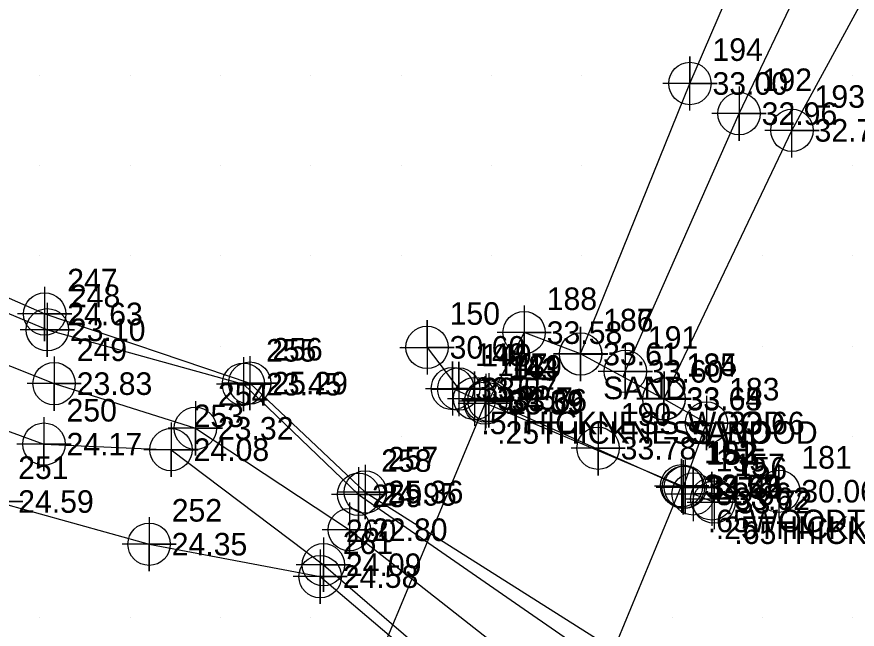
# Model space of a CAD drawing. Extents: x 2204340 to 2204783, y 268170 to 268760.
# Drawn here: x 2204477.4 to 2204570.5, y 268468.7 to 268536.4 of the extents above; entities that cross this region are included whole.
import ezdxf

# ---------------------------------------------------------------- set-up
doc = ezdxf.new("R2010")
doc.units = 0
for name, color, linetype in [('Exist DTM Breakline', 7, 'Continuous'), ('Exist DTM Breakline Cogo Elevation', 7, 'Continuous'), ('Exist DTM Breakline Cogo Number', 7, 'Continuous'), ('Exist DTM Breakline Cogo Point CELL', 7, 'Continuous'), ('Exist DTM Breakline Underwater', 7, 'Continuous'), ('Exist DTM Breakline Underwater Cogo Elevation', 7, 'Continuous'), ('Exist DTM Breakline Underwater Cogo Number', 7, 'Continuous'), ('Exist DTM Breakline Underwater Cogo Point CELL', 7, 'Continuous'), ('Exist DTM Crownline', 7, 'Continuous'), ('Exist DTM Crownline Cogo Elevation', 7, 'Continuous'), ('Exist DTM Crownline Cogo Number', 7, 'Continuous'), ('Exist DTM Crownline Cogo Point CELL', 7, 'Continuous'), ('Exist DTM QL2 LIDAR Elevation Point', 7, 'Continuous'), ('Exist Hydro Jurisdictional Stream or Body of Water', 7, 'Continuous'), ('Exist Roads Change in Surface', 7, 'Continuous'), ('Exist Roads Change in Surface Cogo Comment', 7, 'Continuous'), ('Exist Roads Change in Surface Cogo Elevation', 7, 'Continuous'), ('Exist Roads Change in Surface Cogo Number', 7, 'Continuous'), ('Exist Roads Change in Surface Cogo Point CELL', 7, 'Continuous'), ('Exist Roads EOP', 7, 'Continuous'), ('Exist Roads EOP Cogo Elevation', 7, 'Continuous'), ('Exist Roads EOP Cogo Number', 7, 'Continuous'), ('Exist Roads EOP Cogo Point CELL', 7, 'Continuous'), ('Exist Roads Soil', 7, 'Continuous'), ('Exist Roads Soil Cogo Comment', 7, 'Continuous'), ('Exist Roads Soil Cogo Elevation', 7, 'Continuous'), ('Exist Roads Soil Cogo Number', 7, 'Continuous'), ('Exist Roads Soil Cogo Point CELL', 7, 'Continuous'), ('Exist Structure Major Bridge WW', 7, 'Continuous'), ('Exist Structure Major Bridge WW Cogo Comment', 7, 'Continuous'), ('Exist Structure Major Bridge WW Cogo Elevation', 7, 'Continuous'), ('Exist Structure Major Bridge WW Cogo Number', 7, 'Continuous'), ('Exist Structure Major Bridge WW Cogo Point CELL', 7, 'Continuous'), ('Exist Structure Major Deck Tunnel Box Culvert', 7, 'Continuous'), ('Exist Structure Major Deck Tunnel Box Culvert Cogo Elevation', 7, 'Continuous'), ('Exist Structure Major Deck Tunnel Box Culvert Cogo Number', 7, 'Continuous'), ('Exist Structure Major Deck Tunnel Box Culvert Cogo Point CELL', 7, 'Continuous')]:
    doc.layers.add(name, color=color, linetype=linetype)

msp = doc.modelspace()

# ---------------------------------------------------------------- linework, layer by layer
at = {"layer": 'Exist DTM Breakline'}
for points in [[(2204442.107, 268518.107), (2204480.821, 268501.799), (2204502.532, 268495.779), (2204515.271, 268483.58), (2204555.414, 268455.782), (2204577.652, 268446.314), (2204630.936, 268427.717)], [(2204435.36, 268505.622), (2204480.446, 268489.144), (2204494.514, 268488.53), (2204511.374, 268475.793), (2204547.352, 268444.739), (2204573.727, 268433.567), (2204620.125, 268409.581)]]:
    msp.add_lwpolyline(points, dxfattribs=at)
at = {"layer": 'Exist DTM Breakline Cogo Point CELL'}
for points in [[(2204480.524, 268506.556), (2204480.524, 268500.556), (2204480.524, 268503.556), (2204483.524, 268503.556), (2204477.524, 268503.556)], [(2204480.82, 268504.799), (2204480.82, 268498.799), (2204480.82, 268501.799), (2204483.82, 268501.799), (2204477.82, 268501.799)], [(2204502.531, 268498.779), (2204502.531, 268492.779), (2204502.531, 268495.779), (2204505.531, 268495.779), (2204499.531, 268495.779)], [(2204503.227, 268498.899), (2204503.227, 268492.899), (2204503.227, 268495.899), (2204506.227, 268495.899), (2204500.227, 268495.899)], [(2204480.445, 268492.144), (2204480.445, 268486.144), (2204480.445, 268489.144), (2204483.445, 268489.144), (2204477.445, 268489.144)], [(2204494.513, 268491.53), (2204494.513, 268485.53), (2204494.513, 268488.53), (2204497.513, 268488.53), (2204491.513, 268488.53)], [(2204516.012, 268486.845), (2204516.012, 268480.845), (2204516.012, 268483.845), (2204519.012, 268483.845), (2204513.012, 268483.845)], [(2204475.093, 268485.789), (2204475.093, 268479.789), (2204475.093, 268482.789), (2204478.093, 268482.789), (2204472.093, 268482.789)], [(2204515.27, 268486.58), (2204515.27, 268480.58), (2204515.27, 268483.58), (2204518.27, 268483.58), (2204512.27, 268483.58)], [(2204492.088, 268481.069), (2204492.088, 268475.069), (2204492.088, 268478.069), (2204495.088, 268478.069), (2204489.088, 268478.069)], [(2204511.373, 268478.793), (2204511.373, 268472.793), (2204511.373, 268475.793), (2204514.373, 268475.793), (2204508.373, 268475.793)], [(2204511.02, 268477.48), (2204511.02, 268471.48), (2204511.02, 268474.48), (2204514.02, 268474.48), (2204508.02, 268474.48)]]:
    msp.add_lwpolyline(points, dxfattribs=at)
for centre in [(2204480.524, 268503.556), (2204480.82, 268501.799), (2204502.531, 268495.779), (2204503.227, 268495.899), (2204480.445, 268489.144), (2204494.513, 268488.53), (2204515.27, 268483.58), (2204516.012, 268483.845), (2204492.088, 268478.069), (2204511.373, 268475.793), (2204511.02, 268474.48)]:
    msp.add_circle(centre, 2.344, dxfattribs=at)
at = {"layer": 'Exist DTM Breakline Underwater'}
msp.add_lwpolyline([(2204438.584, 268512.919), (2204481.572, 268495.841), (2204497.204, 268490.895), (2204514.255, 268479.669), (2204552.142, 268449.916), (2204575.996, 268440.349), (2204624.811, 268416.779)], dxfattribs=at)
at = {"layer": 'Exist DTM Breakline Underwater Cogo Point CELL'}
for points in [[(2204481.572, 268498.841), (2204481.572, 268492.841), (2204481.572, 268495.841), (2204484.572, 268495.841), (2204478.572, 268495.841)], [(2204497.203, 268493.895), (2204497.203, 268487.895), (2204497.203, 268490.895), (2204500.203, 268490.895), (2204494.203, 268490.895)], [(2204514.254, 268482.669), (2204514.254, 268476.669), (2204514.254, 268479.669), (2204517.254, 268479.669), (2204511.254, 268479.669)]]:
    msp.add_lwpolyline(points, dxfattribs=at)
for centre in [(2204481.572, 268495.841), (2204497.203, 268490.895), (2204514.254, 268479.669)]:
    msp.add_circle(centre, 2.344, dxfattribs=at)
at = {"layer": 'Exist DTM Crownline'}
msp.add_lwpolyline([(2204544.572, 268496.57), (2204544.796, 268497.202), (2204557.39, 268525.728), (2204578.979, 268570.951), (2204607.648, 268611.861), (2204633.941, 268626.95), (2204664.494, 268629.399), (2204716.626, 268622.98), (2204771.014, 268618.497)], dxfattribs=at)
at = {"layer": 'Exist DTM Crownline Cogo Point CELL'}
for points in [[(2204557.39, 268528.728), (2204557.39, 268522.728), (2204557.39, 268525.728), (2204560.39, 268525.728), (2204554.39, 268525.728)], [(2204544.795, 268500.202), (2204544.795, 268494.202), (2204544.795, 268497.202), (2204547.795, 268497.202), (2204541.795, 268497.202)], [(2204541.788, 268491.69), (2204541.788, 268485.69), (2204541.788, 268488.69), (2204544.788, 268488.69), (2204538.788, 268488.69)]]:
    msp.add_lwpolyline(points, dxfattribs=at)
for centre in [(2204557.39, 268525.728), (2204544.795, 268497.202), (2204541.788, 268488.69)]:
    msp.add_circle(centre, 2.344, dxfattribs=at)
at = {"layer": 'Exist DTM QL2 LIDAR Elevation Point'}
for p, q in [((2204480, 268530), (2204480, 268530)), ((2204490, 268530), (2204490, 268530)), ((2204500, 268530), (2204500, 268530)), ((2204510, 268530), (2204510, 268530)), ((2204520, 268530), (2204520, 268530)), ((2204530, 268530), (2204530, 268530)), ((2204540, 268530), (2204540, 268530)), ((2204550, 268530), (2204550, 268530)), ((2204570, 268530), (2204570, 268530)), ((2204480, 268520), (2204480, 268520)), ((2204490, 268520), (2204490, 268520)), ((2204500, 268520), (2204500, 268520)), ((2204510, 268520), (2204510, 268520)), ((2204520, 268520), (2204520, 268520)), ((2204530, 268520), (2204530, 268520)), ((2204540, 268520), (2204540, 268520)), ((2204570, 268520), (2204570, 268520)), ((2204480, 268510), (2204480, 268510)), ((2204490, 268510), (2204490, 268510)), ((2204500, 268510), (2204500, 268510)), ((2204510, 268510), (2204510, 268510)), ((2204520, 268510), (2204520, 268510)), ((2204530, 268510), (2204530, 268510)), ((2204540, 268510), (2204540, 268510)), ((2204560, 268510), (2204560, 268510)), ((2204570, 268510), (2204570, 268510)), ((2204500, 268500), (2204500, 268500)), ((2204510, 268500), (2204510, 268500)), ((2204520, 268500), (2204520, 268500)), ((2204530, 268500), (2204530, 268500)), ((2204560, 268500), (2204560, 268500)), ((2204570, 268500), (2204570, 268500)), ((2204520, 268490), (2204520, 268490)), ((2204560, 268490), (2204560, 268490)), ((2204570, 268490), (2204570, 268490)), ((2204560, 268480), (2204560, 268480)), ((2204570, 268480), (2204570, 268480)), ((2204480, 268470), (2204480, 268470)), ((2204490, 268470), (2204490, 268470)), ((2204500, 268470), (2204500, 268470)), ((2204510, 268470), (2204510, 268470)), ((2204550, 268470), (2204550, 268470)), ((2204560, 268470), (2204560, 268470)), ((2204570, 268470), (2204570, 268470))]:
    msp.add_line(p, q, dxfattribs=at)
at = {"layer": 'Exist Hydro Jurisdictional Stream or Body of Water'}
for points in [[(2204442.883, 268520.114), (2204480.525, 268503.556), (2204503.227, 268495.899), (2204516.012, 268483.845), (2204556.669, 268458.091), (2204576.766, 268447.287), (2204631.194, 268429.043)], [(2204434.671, 268504.229), (2204475.094, 268482.789), (2204492.089, 268478.069), (2204511.02, 268474.48), (2204547.961, 268443.09), (2204571.955, 268432.882), (2204619.17, 268408.087)]]:
    msp.add_lwpolyline(points, dxfattribs=at)
at = {"layer": 'Exist Roads Change in Surface'}
msp.add_line((2204529.698, 268493.996), (2204551.22, 268484.353), dxfattribs=at)
at = {"layer": 'Exist Roads Change in Surface Cogo Point CELL'}
for points in [[(2204529.352, 268496.909), (2204529.352, 268490.909), (2204529.352, 268493.909), (2204532.352, 268493.909), (2204526.352, 268493.909)], [(2204551.426, 268487.395), (2204551.426, 268481.395), (2204551.426, 268484.395), (2204554.426, 268484.395), (2204548.426, 268484.395)]]:
    msp.add_lwpolyline(points, dxfattribs=at)
for centre in [(2204529.352, 268493.909), (2204551.426, 268484.395)]:
    msp.add_circle(centre, 2.344, dxfattribs=at)
at = {"layer": 'Exist Roads EOP'}
msp.add_lwpolyline([(2204551.22, 268484.353), (2204553.784, 268491.48), (2204549.081, 268494.127), (2204539.853, 268499.128), (2204533.599, 268501.487), (2204529.698, 268493.996)], dxfattribs=at)
at = {"layer": 'Exist Roads EOP Cogo Point CELL'}
for points in [[(2204533.598, 268504.487), (2204533.598, 268498.487), (2204533.598, 268501.487), (2204536.598, 268501.487), (2204530.598, 268501.487)], [(2204539.852, 268502.128), (2204539.852, 268496.128), (2204539.852, 268499.128), (2204542.852, 268499.128), (2204536.852, 268499.128)], [(2204529.697, 268496.996), (2204529.697, 268490.996), (2204529.697, 268493.996), (2204532.697, 268493.996), (2204526.697, 268493.996)], [(2204549.079, 268497.127), (2204549.079, 268491.127), (2204549.079, 268494.127), (2204552.079, 268494.127), (2204546.079, 268494.127)], [(2204553.783, 268494.48), (2204553.783, 268488.48), (2204553.783, 268491.48), (2204556.783, 268491.48), (2204550.783, 268491.48)], [(2204551.219, 268487.354), (2204551.219, 268481.354), (2204551.219, 268484.354), (2204554.219, 268484.354), (2204548.219, 268484.354)]]:
    msp.add_lwpolyline(points, dxfattribs=at)
for centre in [(2204533.598, 268501.487), (2204539.852, 268499.128), (2204529.697, 268493.996), (2204549.079, 268494.127), (2204553.783, 268491.48), (2204551.219, 268484.354)]:
    msp.add_circle(centre, 2.344, dxfattribs=at)
at = {"layer": 'Exist Roads Soil'}
for points in [[(2204539.846, 268499.13), (2204551.949, 268529.067), (2204571.256, 268573.828), (2204604.44, 268616.7), (2204631.803, 268631.708), (2204665.759, 268634.105), (2204716.613, 268627.308), (2204772.216, 268623.542)], [(2204549.081, 268494.183), (2204563.247, 268523.878), (2204586.275, 268566.275), (2204611.477, 268606.181), (2204635.177, 268622.474), (2204662.529, 268625.066), (2204716.085, 268618.662), (2204769.528, 268613.44)]]:
    msp.add_lwpolyline(points, dxfattribs=at)
at = {"layer": 'Exist Roads Soil Cogo Point CELL'}
for points in [[(2204551.949, 268526.066), (2204551.949, 268532.066), (2204551.949, 268529.066), (2204554.949, 268529.066), (2204548.949, 268529.066)], [(2204563.246, 268520.878), (2204563.246, 268526.878), (2204563.246, 268523.878), (2204566.246, 268523.878), (2204560.246, 268523.878)], [(2204539.84, 268496.116), (2204539.84, 268502.116), (2204539.84, 268499.116), (2204542.84, 268499.116), (2204536.84, 268499.116)], [(2204549.081, 268491.184), (2204549.081, 268497.184), (2204549.081, 268494.184), (2204552.081, 268494.184), (2204546.081, 268494.184)]]:
    msp.add_lwpolyline(points, dxfattribs=at)
for centre in [(2204551.949, 268529.066), (2204563.246, 268523.878), (2204539.84, 268499.116), (2204549.081, 268494.184)]:
    msp.add_circle(centre, 2.344, dxfattribs=at)
at = {"layer": 'Exist Structure Major Bridge WW'}
for points in [[(2204522.851, 268499.856), (2204526.362, 268495.246)], [(2204528.113, 268494.186), (2204525.67, 268495.298)], [(2204554.372, 268483.089), (2204561.785, 268483.932)], [(2204552.309, 268483.634), (2204554.63, 268482.725)]]:
    msp.add_lwpolyline(points, dxfattribs=at)
at = {"layer": 'Exist Structure Major Bridge WW Cogo Point CELL'}
for points in [[(2204519.851, 268499.856), (2204525.851, 268499.856), (2204522.851, 268499.856), (2204522.851, 268502.856), (2204522.851, 268496.856)], [(2204522.669, 268495.298), (2204528.669, 268495.298), (2204525.669, 268495.298), (2204525.669, 268498.298), (2204525.669, 268492.298)], [(2204523.361, 268495.246), (2204529.361, 268495.246), (2204526.361, 268495.246), (2204526.361, 268498.246), (2204526.361, 268492.246)], [(2204525.112, 268494.186), (2204531.112, 268494.186), (2204528.112, 268494.186), (2204528.112, 268497.186), (2204528.112, 268491.186)], [(2204558.784, 268483.932), (2204564.784, 268483.932), (2204561.784, 268483.932), (2204561.784, 268486.932), (2204561.784, 268480.932)], [(2204549.309, 268483.634), (2204555.309, 268483.634), (2204552.309, 268483.634), (2204552.309, 268486.634), (2204552.309, 268480.634)], [(2204551.371, 268483.089), (2204557.371, 268483.089), (2204554.371, 268483.089), (2204554.371, 268486.089), (2204554.371, 268480.089)], [(2204551.629, 268482.725), (2204557.629, 268482.725), (2204554.629, 268482.725), (2204554.629, 268485.725), (2204554.629, 268479.725)]]:
    msp.add_lwpolyline(points, dxfattribs=at)
for centre in [(2204522.851, 268499.856), (2204525.669, 268495.298), (2204526.361, 268495.246), (2204528.112, 268494.186), (2204552.309, 268483.634), (2204561.784, 268483.932), (2204554.371, 268483.089), (2204554.629, 268482.725)]:
    msp.add_circle(centre, 2.344, dxfattribs=at)
at = {"layer": 'Exist Structure Major Deck Tunnel Box Culvert'}
msp.add_lwpolyline([(2204531.382, 268437.017), (2204551.027, 268484.531), (2204529.29, 268493.682), (2204509.543, 268446.369)], close=True, dxfattribs=at)
at = {"layer": 'Exist Structure Major Deck Tunnel Box Culvert Cogo Point CELL'}
for points in [[(2204526.29, 268493.682), (2204532.29, 268493.682), (2204529.29, 268493.682), (2204529.29, 268496.682), (2204529.29, 268490.682)], [(2204548.027, 268484.531), (2204554.027, 268484.531), (2204551.027, 268484.531), (2204551.027, 268487.531), (2204551.027, 268481.531)]]:
    msp.add_lwpolyline(points, dxfattribs=at)
for centre in [(2204529.29, 268493.682), (2204551.027, 268484.531)]:
    msp.add_circle(centre, 2.344, dxfattribs=at)

# ---------------------------------------------------------------- texts
at = {"layer": 'Exist DTM Breakline Cogo Elevation'}
for s, p in [('24.63', (2204483.024, 268502.306)), ('23.10', (2204483.32, 268500.549)), ('23.45', (2204505.031, 268494.529)), ('25.29', (2204505.727, 268494.649)), ('24.17', (2204482.945, 268487.894)), ('24.08', (2204497.013, 268487.28)), ('24.95', (2204517.77, 268482.33)), ('25.36', (2204518.512, 268482.595)), ('24.59', (2204477.593, 268481.539)), ('24.35', (2204494.588, 268476.819)), ('24.09', (2204513.873, 268474.543)), ('24.58', (2204513.52, 268473.23))]:
    msp.add_text(s, height=2.5, dxfattribs=at).set_placement(p)
at = {"layer": 'Exist DTM Breakline Cogo Number'}
for s, p in [('247', (2204483.024, 268506.056)), ('248', (2204483.32, 268504.299)), ('255', (2204505.031, 268498.279)), ('256', (2204505.727, 268498.399)), ('250', (2204482.945, 268491.644)), ('253', (2204497.013, 268491.03)), ('258', (2204517.77, 268486.08)), ('257', (2204518.512, 268486.345)), ('251', (2204477.593, 268485.289)), ('252', (2204494.588, 268480.569)), ('260', (2204513.873, 268478.293)), ('261', (2204513.52, 268476.98))]:
    msp.add_text(s, height=2.5, dxfattribs=at).set_placement(p)
at = {"layer": 'Exist DTM Breakline Underwater Cogo Elevation'}
for s, p in [('23.83', (2204484.072, 268494.591)), ('23.32', (2204499.703, 268489.645)), ('22.80', (2204516.754, 268478.419))]:
    msp.add_text(s, height=2.5, dxfattribs=at).set_placement(p)
at = {"layer": 'Exist DTM Breakline Underwater Cogo Number'}
for s, p in [('249', (2204484.072, 268498.341)), ('254', (2204499.703, 268493.395)), ('259', (2204516.754, 268482.169))]:
    msp.add_text(s, height=2.5, dxfattribs=at).set_placement(p)
at = {"layer": 'Exist DTM Crownline Cogo Elevation'}
for s, p in [('32.96', (2204559.89, 268524.478)), ('33.60', (2204547.295, 268495.952)), ('33.78', (2204544.288, 268487.44))]:
    msp.add_text(s, height=2.5, dxfattribs=at).set_placement(p)
at = {"layer": 'Exist DTM Crownline Cogo Number'}
for s, p in [('192', (2204559.89, 268528.228)), ('191', (2204547.295, 268499.702)), ('190', (2204544.288, 268491.19))]:
    msp.add_text(s, height=2.5, dxfattribs=at).set_placement(p)
at = {"layer": 'Exist Roads Change in Surface Cogo Comment'}
msp.add_text('.65WOODTHICKNESS', height=2.5, dxfattribs=at).set_placement((2204553.926, 268479.395))
at = {"layer": 'Exist Roads Change in Surface Cogo Elevation'}
for s, p in [('34.39', (2204531.852, 268492.659)), ('34.46', (2204553.926, 268483.145))]:
    msp.add_text(s, height=2.5, dxfattribs=at).set_placement(p)
at = {"layer": 'Exist Roads Change in Surface Cogo Number'}
for s, p in [('144', (2204531.852, 268496.409)), ('152', (2204553.926, 268486.895))]:
    msp.add_text(s, height=2.5, dxfattribs=at).set_placement(p)
at = {"layer": 'Exist Roads EOP Cogo Elevation'}
for s, p in [('33.58', (2204536.098, 268500.237)), ('33.61', (2204542.352, 268497.878)), ('33.66', (2204532.197, 268492.746)), ('33.65', (2204551.579, 268492.877)), ('33.66', (2204556.283, 268490.23)), ('33.62', (2204553.719, 268483.104))]:
    msp.add_text(s, height=2.5, dxfattribs=at).set_placement(p)
at = {"layer": 'Exist Roads EOP Cogo Number'}
for s, p in [('188', (2204536.098, 268503.987)), ('187', (2204542.352, 268501.628)), ('189', (2204532.197, 268496.496)), ('184', (2204551.579, 268496.627)), ('183', (2204556.283, 268493.98)), ('182', (2204553.719, 268486.854))]:
    msp.add_text(s, height=2.5, dxfattribs=at).set_placement(p)
at = {"layer": 'Exist Roads Soil Cogo Comment'}
for p in [(2204542.34, 268494.116), (2204551.581, 268489.184)]:
    msp.add_text('SAND', height=2.5, dxfattribs=at).set_placement(p)
at = {"layer": 'Exist Roads Soil Cogo Elevation'}
for s, p in [('33.00', (2204554.449, 268527.816)), ('32.77', (2204565.746, 268522.628)), ('33.61', (2204542.34, 268497.866)), ('33.64', (2204551.581, 268492.934))]:
    msp.add_text(s, height=2.5, dxfattribs=at).set_placement(p)
at = {"layer": 'Exist Roads Soil Cogo Number'}
for s, p in [('194', (2204554.449, 268531.566)), ('193', (2204565.746, 268526.378)), ('186', (2204542.34, 268501.616)), ('185', (2204551.581, 268496.684))]:
    msp.add_text(s, height=2.5, dxfattribs=at).set_placement(p)
at = {"layer": 'Exist Structure Major Bridge WW Cogo Comment'}
for s, p in [('.5THICKNESS WOOD', (2204528.861, 268490.246)), ('.25THICKNESS WOOD', (2204530.612, 268489.186)), ('.25THICKNESS', (2204554.809, 268478.634)), ('.65THICKNESS WOOD', (2204556.871, 268478.089))]:
    msp.add_text(s, height=2.5, dxfattribs=at).set_placement(p)
at = {"layer": 'Exist Structure Major Bridge WW Cogo Elevation'}
for s, p in [('30.60', (2204525.351, 268498.606)), ('33.55', (2204528.169, 268494.048)), ('33.57', (2204528.861, 268493.996)), ('33.57', (2204530.612, 268492.936)), ('33.66', (2204554.809, 268482.384)), ('30.06', (2204564.284, 268482.682)), ('33.62', (2204556.871, 268481.839)), ('33.72', (2204557.129, 268481.475))]:
    msp.add_text(s, height=2.5, dxfattribs=at).set_placement(p)
at = {"layer": 'Exist Structure Major Bridge WW Cogo Number'}
for s, p in [('150', (2204525.351, 268502.356)), ('148', (2204528.169, 268497.798)), ('149', (2204528.861, 268497.746)), ('147', (2204530.612, 268496.686)), ('155', (2204554.809, 268486.134)), ('181', (2204564.284, 268486.432)), ('157', (2204556.871, 268485.589)), ('156', (2204557.129, 268485.225))]:
    msp.add_text(s, height=2.5, dxfattribs=at).set_placement(p)
at = {"layer": 'Exist Structure Major Deck Tunnel Box Culvert Cogo Elevation'}
for s, p in [('33.59', (2204531.79, 268492.432)), ('33.58', (2204553.527, 268483.281))]:
    msp.add_text(s, height=2.5, dxfattribs=at).set_placement(p)
at = {"layer": 'Exist Structure Major Deck Tunnel Box Culvert Cogo Number'}
for s, p in [('143', (2204531.79, 268496.182)), ('151', (2204553.527, 268487.031))]:
    msp.add_text(s, height=2.5, dxfattribs=at).set_placement(p)

doc.saveas('drawing.dxf')
